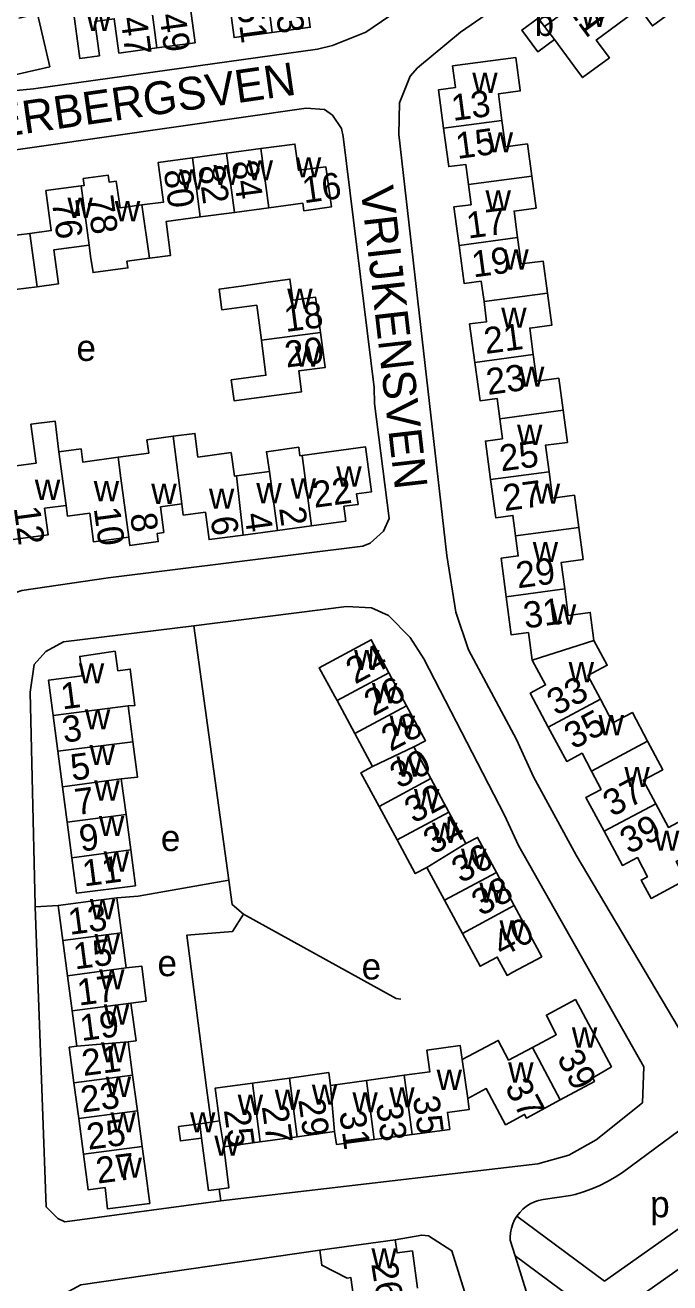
# Model space of a CAD drawing. Extents: x 162667 to 164645, y 379003 to 382150.
# Drawn here: x 163598 to 163696.1, y 381098.1 to 381289.7 of the extents above; entities that cross this region are included whole.
import ezdxf

# ---------------------------------------------------------------- set-up
doc = ezdxf.new("R2010")
doc.units = 0
for name, color, linetype in [('BLT_Basislijn', 7, 'Continuous'), ('BLT_Bebouwing', 7, 'Continuous'), ('BLT_Centroide', 7, 'Continuous'), ('BLT_Huisnummer', 7, 'Continuous'), ('BLT_Huisnummer_ tussenligend', 7, 'Continuous'), ('BLT_Onderverdeling_panden', 7, 'Continuous'), ('BLT_Straatnaam', 7, 'Continuous')]:
    doc.layers.add(name, color=color, linetype=linetype)

msp = doc.modelspace()

# ---------------------------------------------------------------- linework, layer by layer
at = {"layer": 'BLT_Basislijn'}
for p, q in [((163664.25, 381288.62), (163682.77, 381301.43)), ((163657.72, 381283.2), (163664.25, 381288.62)), ((163656.59, 381281.91), (163657.72, 381283.2)), ((163654.95, 381277.85), (163656.59, 381281.91)), ((163654.87, 381273.04), (163654.95, 381277.85)), ((163662.19, 381208.9), (163654.87, 381273.04)), ((163663.55, 381200.26), (163662.19, 381208.9)), ((163665.46, 381194.53), (163663.55, 381200.26)), ((163623.65, 381198.19), (163629, 381159.43)), ((163672.79, 381180.88), (163665.46, 381194.53)), ((163675.4, 381175.21), (163672.79, 381180.88)), ((163681.89, 381163.26), (163675.4, 381175.21)), ((163698.35, 381135.41), (163681.89, 381163.26)), ((163603, 381155.59), (163599.49, 381155.39)), ((163698.9, 381122.3), (163688.93, 381114.94)), ((163686.19, 381098.35), (163706.26, 381112.53)), ((163676.84, 381110.81), (163681.01, 381111.4)), ((163672.83, 381108.25), (163686.19, 381098.35)), ((163688.46, 381093.84), (163709.27, 381108.53)), ((163671.82, 381104.61), (163672.58, 381102.22)), ((163672.58, 381102.22), (163701.62, 381010.06))]:
    msp.add_line(p, q, dxfattribs=at)
for points in [[(163704.62, 381348.91), (163712.56, 381338.33), (163712.43, 381333.8), (163710.39, 381331.86), (163675.03, 381306.44), (163666.11, 381299.73), (163649.85, 381288.62), (163644.75, 381286.58), (163642.47, 381286.05), (163599.25, 381280), (163589.15, 381279.05), (163586.28, 381280.4), (163584.72, 381282.62), (163582.01, 381293.43), (163574.46, 381327.24), (163571.73, 381328.85), (163571.41, 381330.34)], [(163583.1, 381270.55), (163587.28, 381269.85), (163590.17, 381269.81), (163640.77, 381277.05), (163643.57, 381276.83), (163644.77, 381275.96), (163646.12, 381273.96), (163646.38, 381272.71), (163651.1, 381234.51), (163651.18, 381232.05), (163653.39, 381214.56), (163652.55, 381212.63), (163650.49, 381210.78), (163649.37, 381210.33), (163610.61, 381205.49), (163597.45, 381203.58), (163592.38, 381201.9)], [(163623.65, 381198.19), (163646.89, 381201.14), (163650.71, 381200.95), (163653.29, 381199.78), (163656.57, 381196.41), (163658.68, 381193.16), (163670.98, 381169.35), (163673.09, 381164.73), (163692.18, 381131.03), (163691.97, 381125.54), (163684.9, 381119.9), (163680.76, 381117.58), (163676.04, 381116.22), (163627.76, 381110.58)], [(163623.65, 381198.19), (163603.81, 381195.76), (163601.09, 381194.3), (163599.33, 381192.3), (163598.72, 381188.1), (163599.48, 381155.59), (163599.49, 381155.39)], [(163629, 381159.43), (163615.18, 381157.02), (163611.92, 381156.78)], [(163631.23, 381154.27), (163629.51, 381155.72), (163629, 381159.43)], [(163599.49, 381155.39), (163601.16, 381109.67), (163602.92, 381107.89), (163604.01, 381107.39), (163627.76, 381110.58)], [(163626.27, 381122.59), (163625.59, 381127.82), (163622.61, 381151.08), (163629.55, 381151.64), (163631.23, 381154.27)], [(163631.23, 381154.27), (163654.48, 381141.43), (163655.17, 381141.31)], [(163688.93, 381114.94), (163687.82, 381114.2), (163686.67, 381113.53), (163685.48, 381112.93), (163684.26, 381112.41), (163683.01, 381111.95), (163681.73, 381111.58), (163681.01, 381111.4)], [(163627.76, 381110.58), (163627.53, 381112.4)], [(163676.84, 381110.81), (163676.16, 381110.66), (163675.51, 381110.44), (163674.89, 381110.14), (163674.31, 381109.77), (163673.77, 381109.34), (163673.29, 381108.85), (163672.83, 381108.25)], [(163672.83, 381108.25), (163672.5, 381107.71), (163672.22, 381107.08), (163672.01, 381106.43), (163671.87, 381105.75), (163671.82, 381105.06), (163671.82, 381104.61)], [(163654.3, 381104.67), (163658.36, 381105.39), (163659.41, 381105.28), (163662.92, 381103.01), (163692.54, 381007.91)], [(163615.57, 381000.96), (163602.69, 381093.3), (163604.03, 381096.48), (163606.45, 381097.82), (163642.82, 381103.11)], [(163672.58, 381102.22), (163683.03, 381094.47), (163694.24, 381058.06)]]:
    msp.add_lwpolyline(points, dxfattribs=at)
at = {"layer": 'BLT_Bebouwing'}
for p, q in [((163628.65, 381270.18), (163623.44, 381269.49)), ((163633.85, 381270.88), (163628.65, 381270.18)), ((163635.05, 381261.86), (163629.85, 381261.17)), ((163629.85, 381261.17), (163624.64, 381260.48)), ((163612.51, 381220.7), (163612.13, 381223.87)), ((163630.15, 381221.04), (163635.17, 381221.72)), ((163600.91, 381216.09), (163604.2, 381216.54)), ((163618.55, 381216.31), (163621.83, 381216.75)), ((163636.39, 381212.73), (163631.18, 381212.02)), ((163641.59, 381213.43), (163636.39, 381212.73)), ((163653.36, 381191.05), (163656.06, 381186.03)), ((163613.64, 381186.01), (163614.37, 381180.54)), ((163645.46, 381186.8), (163648.17, 381181.78)), ((163602.95, 381179.1), (163602.24, 381184.51)), ((163648.17, 381181.78), (163650.87, 381176.76)), ((163657.17, 381179.74), (163659.75, 381174.93)), ((163603.66, 381173.69), (163602.95, 381179.1)), ((163604.37, 381168.28), (163603.66, 381173.69)), ((163612.61, 381174.86), (163613.33, 381169.46)), ((163659.75, 381174.93), (163662.5, 381169.81)), ((163651.85, 381170.69), (163654.61, 381165.57)), ((163662.5, 381169.81), (163665.08, 381165.01)), ((163605.08, 381162.87), (163604.37, 381168.28)), ((163613.33, 381169.46), (163614.04, 381164.05)), ((163659.13, 381161.4), (163661.83, 381156.38)), ((163669.72, 381160.62), (163672.43, 381155.6)), ((163611.92, 381156.78), (163612.64, 381151.42)), ((163661.83, 381156.38), (163664.54, 381151.35)), ((163603.71, 381150.24), (163603, 381155.59)), ((163612.64, 381151.42), (163613.36, 381146.07)), ((163604.42, 381144.88), (163603.71, 381150.24)), ((163605.12, 381139.53), (163604.42, 381144.88)), ((163605.83, 381134.18), (163605.12, 381139.53)), ((163613.65, 381134.82), (163614.33, 381129.77)), ((163614.33, 381129.77), (163615.06, 381124.33)), ((163655.68, 381129.73), (163649.93, 381128.94)), ((163606.13, 381123.14), (163605.4, 381128.57)), ((163638.2, 381129.31), (163632.56, 381128.54)), ((163649.93, 381128.94), (163644.46, 381128.19)), ((163615.06, 381124.33), (163615.79, 381118.9)), ((163606.86, 381117.71), (163606.13, 381123.14)), ((163639.41, 381120.37), (163633.77, 381119.61)), ((163645.05, 381121.14), (163639.41, 381120.37)), ((163656.88, 381120.71), (163651.13, 381119.95)), ((163657.71, 381097.3), (163656.93, 381102.98))]:
    msp.add_line(p, q, dxfattribs=at)
for points in [[(163677.04, 381289.47), (163679.72, 381291.46), (163678.15, 381293.57), (163682.88, 381297.07)], [(163635.59, 381288.58), (163641.37, 381289.36), (163640.75, 381294.12), (163644.78, 381294.65)], [(163608.21, 381292.94), (163605.24, 381292.55), (163606.28, 381284.63), (163609.27, 381285.02), (163608.57, 381290.27)], [(163618.04, 381286.22), (163623.83, 381287), (163623.13, 381292.25), (163626.11, 381292.65)], [(163626.11, 381292.65), (163629.07, 381293.05), (163629.78, 381287.8), (163635.59, 381288.58)], [(163697.44, 381292.49), (163693.49, 381289.57), (163691.5, 381292.26), (163688.22, 381289.84)], [(163588.21, 381288.69), (163588.9, 381285.76), (163587.44, 381285.42), (163588.07, 381282.65), (163595.16, 381284.3), (163595.71, 381281.95), (163601.7, 381283.35), (163599.83, 381291.4), (163596.99, 381290.74)], [(163608.57, 381290.27), (163611.53, 381290.66), (163612.24, 381285.44), (163618.04, 381286.22)], [(163677.04, 381289.47), (163676.07, 381290.78), (163673.6, 381288.93), (163676.03, 381285.64), (163678.55, 381287.5)], [(163688.22, 381289.84), (163684.94, 381287.42), (163686.93, 381284.73), (163682.84, 381281.7), (163681.52, 381283.48), (163678.55, 381287.5)], [(163661.67, 381273.99), (163660.89, 381279.82), (163663.49, 381280.18), (163663.06, 381283.47), (163672.68, 381284.75), (163673.35, 381279.79), (163673.37, 381279.67), (163670.03, 381279.22), (163670.57, 381275.19)], [(163675.1, 381266.71), (163674.45, 381271.6), (163671.11, 381271.15), (163670.57, 381275.19)], [(163665.46, 381265.42), (163665.06, 381268.49), (163662.46, 381268.16), (163661.67, 381273.99)], [(163635.05, 381261.86), (163640.26, 381262.55), (163640.41, 381261.42), (163644.59, 381262), (163643.73, 381268.12), (163639.58, 381267.58), (163639.05, 381271.58), (163633.85, 381270.88)], [(163623.44, 381269.49), (163618.23, 381268.79), (163618.89, 381263.83), (163619.04, 381262.74), (163615.72, 381262.3)], [(163612.45, 381261.86), (163611.83, 381265.92), (163610.76, 381265.77), (163610.62, 381266.83), (163606.8, 381266.32), (163606.94, 381265.26), (163606.48, 381265.2)], [(163664.05, 381256.15), (163663.26, 381262), (163665.86, 381262.34), (163665.46, 381265.42)], [(163672.96, 381257.34), (163672.42, 381261.38), (163675.76, 381261.82), (163675.1, 381266.71)], [(163606.48, 381265.2), (163601.13, 381264.48), (163601.94, 381258.41), (163598.68, 381257.97)], [(163589.45, 381260.88), (163594.8, 381261.59), (163595.34, 381257.53), (163598.68, 381257.97)], [(163615.72, 381262.3), (163612.45, 381261.86)], [(163616.88, 381254.18), (163620.12, 381254.61), (163619.43, 381259.78), (163624.64, 381260.48)], [(163599.78, 381249.85), (163603.04, 381250.28), (163602.34, 381255.47), (163607.69, 381256.19)], [(163607.69, 381256.19), (163607.92, 381254.48), (163608.31, 381251.99), (163613.61, 381252.7), (163613.47, 381253.72), (163616.88, 381254.18)], [(163667.84, 381247.58), (163667.52, 381250), (163667.43, 381250.67), (163664.84, 381250.33), (163664.05, 381256.15)], [(163677.49, 381248.87), (163676.84, 381253.76), (163673.5, 381253.31), (163672.96, 381257.34)], [(163599.78, 381249.85), (163596.42, 381249.4), (163595.99, 381252.6), (163590.65, 381251.89)], [(163633.93, 381241.69), (163633.22, 381247.03), (163627.92, 381246.32), (163627.5, 381249.47), (163631.23, 381250), (163634.96, 381250.53), (163638.29, 381251.01), (163638.72, 381247.78), (163642.2, 381248.24), (163642.92, 381242.88)], [(163675.35, 381239.5), (163674.81, 381243.54), (163678.15, 381243.98), (163677.49, 381248.87)], [(163666.44, 381238.31), (163665.65, 381244.17), (163668.24, 381244.52), (163667.84, 381247.58)], [(163642.92, 381242.88), (163643.63, 381237.54), (163639.63, 381237.01), (163640.05, 381233.84), (163629.78, 381232.48), (163629.36, 381235.65), (163634.64, 381236.35), (163633.93, 381241.69)], [(163679.88, 381231.02), (163679.23, 381235.91), (163675.89, 381235.47), (163675.35, 381239.5)], [(163670.24, 381229.74), (163669.83, 381232.84), (163667.23, 381232.49), (163666.44, 381238.31)], [(163677.74, 381221.66), (163677.2, 381225.69), (163680.54, 381226.14), (163679.88, 381231.02)], [(163594.66, 381222.33), (163599.64, 381222.95), (163598.85, 381228.9), (163602.52, 381229.38), (163603.1, 381224.68)], [(163668.84, 381220.47), (163668.05, 381226.34), (163670.65, 381226.69), (163670.24, 381229.74)], [(163612.13, 381223.87), (163616.79, 381224.5), (163616.51, 381226.52), (163620.5, 381227.06)], [(163620.5, 381227.06), (163623.81, 381227.5), (163624.28, 381223.9), (163629.33, 381224.59)], [(163603.1, 381224.68), (163606.47, 381225.15), (163606.74, 381223.13), (163612.13, 381223.87)], [(163635.17, 381221.72), (163634.71, 381224.72), (163639.63, 381225.39), (163639.8, 381224.09), (163640.14, 381224.14)], [(163646.47, 381216.42), (163648.67, 381216.69), (163648.44, 381218.3), (163650.69, 381218.6), (163649.77, 381225.47), (163640.14, 381224.14)], [(163629.33, 381224.59), (163629.82, 381221), (163630.15, 381221.04)], [(163682.27, 381213.19), (163681.62, 381218.08), (163678.28, 381217.63), (163677.74, 381221.66)], [(163672.65, 381211.9), (163672.23, 381215), (163669.63, 381214.65), (163668.84, 381220.47)], [(163596.12, 381211.32), (163601.46, 381212.05), (163600.91, 381216.09)], [(163604.2, 381216.54), (163604.41, 381214.92), (163607.79, 381215.37)], [(163613.73, 381211.69), (163613.9, 381210.44), (163618.24, 381211.03), (163618.07, 381212.28), (163619.07, 381212.41), (163618.55, 381216.31)], [(163621.83, 381216.75), (163622.04, 381215.07), (163625.42, 381215.52)], [(163646.47, 381216.42), (163646.78, 381214.14), (163641.59, 381213.43)], [(163607.79, 381215.37), (163608.38, 381210.97), (163613.73, 381211.69)], [(163631.18, 381212.02), (163625.98, 381211.32), (163625.42, 381215.52)], [(163671.23, 381202.63), (163670.45, 381208.48), (163673.06, 381208.83), (163672.65, 381211.9)], [(163680.14, 381203.83), (163679.6, 381207.86), (163682.92, 381208.3), (163682.27, 381213.19)], [(163675.19, 381192.95), (163674.61, 381197.17), (163672, 381196.81), (163671.23, 381202.63)], [(163684.57, 381195.97), (163684.01, 381200.24), (163680.68, 381199.79), (163680.14, 381203.83)], [(163653.36, 381191.05), (163650.66, 381196.07), (163642.76, 381191.81), (163645.13, 381187.41), (163645.46, 381186.8)], [(163685.57, 381187), (163683.65, 381190.61), (163686.61, 381192.18), (163684.57, 381195.97)], [(163602.24, 381184.51), (163601.53, 381189.92), (163606.65, 381190.6), (163606.27, 381193.54), (163611.67, 381194.33), (163612.1, 381191.36), (163613.96, 381191.61), (163614.68, 381186.08), (163613.64, 381186.01)], [(163677.63, 381182.78), (163674.87, 381187.93), (163677.21, 381189.19), (163675.19, 381192.95)], [(163692.76, 381180.61), (163690.44, 381184.97), (163687.48, 381183.39), (163685.57, 381187)], [(163656.06, 381186.03), (163658.94, 381180.69), (163657.17, 381179.74)], [(163684.21, 381176.07), (163682.77, 381178.78), (163680.44, 381177.55), (163677.63, 381182.78)], [(163614.37, 381180.54), (163615.08, 381175.16), (163612.61, 381174.86)], [(163694.01, 381171.08), (163692.09, 381174.68), (163695.07, 381176.26), (163692.76, 381180.61)], [(163650.87, 381176.76), (163649.1, 381175.81), (163651.85, 381170.69)], [(163686.12, 381166.89), (163683.36, 381172.05), (163685.68, 381173.28), (163684.21, 381176.07)], [(163694.01, 381171.08), (163695.92, 381167.49), (163698.9, 381169.07), (163701.3, 381164.56), (163697.08, 381162.31), (163698.58, 381159.5), (163697.69, 381159.03), (163693.28, 381156.68), (163691.77, 381159.46), (163692.73, 381159.96), (163691.21, 381162.88), (163688.91, 381161.69), (163686.12, 381166.89)], [(163665.08, 381165.01), (163666.85, 381165.96), (163669.72, 381160.62)], [(163614.04, 381164.05), (163614.76, 381158.61), (163605.79, 381157.46), (163605.08, 381162.87)], [(163654.61, 381165.57), (163657.36, 381160.44), (163659.13, 381161.4)], [(163603, 381155.59), (163607.96, 381156.25), (163611.92, 381156.78)], [(163664.54, 381151.35), (163667.24, 381146.33), (163669.85, 381147.74), (163671.35, 381144.95), (163672.24, 381145.42), (163676.64, 381147.79), (163672.43, 381155.6)], [(163613.36, 381146.07), (163615.71, 381146.36), (163616.38, 381141.01), (163614.08, 381140.72)], [(163679.43, 381125.98), (163684.66, 381128.8), (163684.4, 381129.34), (163687.23, 381131.02), (163681.77, 381141.25), (163677.35, 381138.91), (163678.83, 381135.89), (163675.21, 381133.97)], [(163614.08, 381140.72), (163614.85, 381134.98), (163613.65, 381134.82)], [(163605.4, 381128.57), (163604.68, 381134.01), (163605.83, 381134.18)], [(163664.52, 381132.13), (163664.22, 381134.26), (163659.15, 381133.56), (163659.6, 381130.27), (163655.68, 381129.73)], [(163675.21, 381133.97), (163671.58, 381132.05), (163670.01, 381135.03), (163664.52, 381132.13)], [(163644.46, 381128.19), (163644.19, 381130.14), (163638.2, 381129.31)], [(163632.56, 381128.54), (163626.89, 381127.76), (163627.58, 381122.77)], [(163679.43, 381125.98), (163674.31, 381123.22), (163674.01, 381123.76), (163671.12, 381122.19), (163668.19, 381127.7), (163665.36, 381126.19)], [(163665.36, 381126.19), (163665.57, 381124.5), (163662.28, 381124.08), (163662.63, 381121.48), (163656.88, 381120.71)], [(163624.54, 381122.35), (163621.32, 381121.91), (163621.62, 381119.72), (163624.83, 381120.16)], [(163626.27, 381122.59), (163624.54, 381122.35)], [(163627.58, 381122.77), (163626.27, 381122.59)], [(163624.83, 381120.16), (163625.89, 381112.18), (163627.53, 381112.4)], [(163651.13, 381119.95), (163645.38, 381119.18), (163645.05, 381121.14)], [(163615.79, 381118.9), (163616.28, 381115.18), (163616.94, 381110.22), (163610.52, 381109.37), (163610.13, 381112.61), (163607.58, 381112.27), (163606.86, 381117.71)], [(163627.53, 381112.4), (163629, 381112.59), (163628.2, 381118.85)], [(163628.2, 381118.85), (163633.77, 381119.61)], [(163654.3, 381104.67), (163642.82, 381103.11)], [(163656.93, 381102.98), (163654.59, 381102.66), (163654.3, 381104.67)], [(163642.82, 381103.11), (163643.14, 381100.79), (163646.98, 381098.84), (163647.58, 381098.92), (163647.99, 381095.96)]]:
    msp.add_lwpolyline(points, dxfattribs=at)
at = {"layer": 'BLT_Onderverdeling_panden'}
for p, q in [((163618.04, 381286.22), (163616.64, 381296.6)), ((163634.38, 381297.48), (163635.59, 381288.58)), ((163670.57, 381275.19), (163661.67, 381273.99)), ((163624.64, 381260.48), (163623.44, 381269.49)), ((163629.85, 381261.17), (163628.65, 381270.18)), ((163635.05, 381261.86), (163633.85, 381270.88)), ((163675.1, 381266.71), (163665.46, 381265.42)), ((163606.48, 381265.2), (163607.69, 381256.19)), ((163615.72, 381262.3), (163616.88, 381254.18)), ((163598.68, 381257.97), (163599.78, 381249.85)), ((163672.96, 381257.34), (163664.05, 381256.15)), ((163677.49, 381248.87), (163667.84, 381247.58)), ((163633.93, 381241.69), (163642.92, 381242.88)), ((163675.35, 381239.5), (163666.44, 381238.31)), ((163679.88, 381231.02), (163670.24, 381229.74)), ((163621.83, 381216.75), (163620.5, 381227.06)), ((163603.1, 381224.68), (163604.2, 381216.54)), ((163641.59, 381213.43), (163640.14, 381224.14)), ((163636.39, 381212.73), (163635.17, 381221.72)), ((163677.74, 381221.66), (163668.84, 381220.47)), ((163612.51, 381220.7), (163613.73, 381211.69)), ((163631.18, 381212.02), (163630.15, 381221.04)), ((163682.27, 381213.19), (163672.65, 381211.9)), ((163680.14, 381203.83), (163671.23, 381202.63)), ((163675.19, 381192.95), (163684.57, 381195.97)), ((163653.36, 381191.05), (163645.46, 381186.8)), ((163685.57, 381187), (163677.63, 381182.78)), ((163613.64, 381186.01), (163602.24, 381184.51)), ((163656.06, 381186.03), (163648.17, 381181.78)), ((163614.37, 381180.54), (163602.95, 381179.1)), ((163650.87, 381176.76), (163657.17, 381179.74)), ((163692.76, 381180.61), (163684.21, 381176.07)), ((163612.61, 381174.86), (163603.66, 381173.69)), ((163659.75, 381174.93), (163651.85, 381170.69)), ((163662.5, 381169.81), (163654.61, 381165.57)), ((163694.01, 381171.08), (163686.12, 381166.89)), ((163613.33, 381169.46), (163604.37, 381168.28)), ((163614.04, 381164.05), (163605.08, 381162.87)), ((163665.08, 381165.01), (163659.13, 381161.4)), ((163669.72, 381160.62), (163661.83, 381156.38)), ((163672.43, 381155.6), (163664.54, 381151.35)), ((163612.64, 381151.42), (163603.71, 381150.24)), ((163613.36, 381146.07), (163604.42, 381144.88)), ((163614.08, 381140.72), (163605.12, 381139.53)), ((163605.83, 381134.18), (163613.65, 381134.82)), ((163675.21, 381133.97), (163679.43, 381125.98)), ((163664.52, 381132.13), (163665.36, 381126.19)), ((163614.33, 381129.77), (163605.4, 381128.57)), ((163656.88, 381120.71), (163655.68, 381129.73)), ((163633.77, 381119.61), (163632.56, 381128.54)), ((163639.41, 381120.37), (163638.2, 381129.31)), ((163644.46, 381128.19), (163645.05, 381121.14)), ((163651.13, 381119.95), (163649.93, 381128.94)), ((163615.06, 381124.33), (163606.13, 381123.14)), ((163624.54, 381122.35), (163624.83, 381120.16)), ((163627.58, 381122.77), (163628.2, 381118.85)), ((163615.79, 381118.9), (163606.86, 381117.71))]:
    msp.add_line(p, q, dxfattribs=at)
msp.add_lwpolyline([(163678.55, 381287.5), (163677.04, 381289.47)], dxfattribs=at)

# ---------------------------------------------------------------- texts
at = {"layer": 'BLT_Centroide'}
for s, p in [('b', (163675.54, 381288.05)), ('w', (163682.62, 381289.42)), ('w', (163607.25, 381288.78)), ('w', (163666.05, 381279.38)), ('w', (163668.4, 381270.31)), ('w', (163639.2, 381266.5)), ('w', (163621.44, 381264.64)), ('w', (163626.64, 381265.33)), ('w', (163631.84, 381266.03)), ('w', (163668.07, 381261.44)), ('w', (163604.41, 381260.33)), ('w', (163611.62, 381259.81)), ('w', (163670.78, 381252.47)), ('w', (163637.87, 381246.47)), ('w', (163670.46, 381243.59)), ('e', (163605.77, 381238.54)), ('w', (163639.03, 381237.69)), ('w', (163673.17, 381234.62)), ('w', (163672.87, 381225.75)), ('w', (163645.34, 381219.41)), ('w', (163599.44, 381217.36)), ('w', (163608.41, 381217.17)), ('w', (163617.17, 381216.75)), ('w', (163633.17, 381216.86)), ('w', (163638.38, 381217.58)), ('w', (163675.57, 381216.78)), ('w', (163625.95, 381216.03)), ('w', (163675.26, 381207.91)), ('w', (163678.02, 381198.38)), ('w', (163648.06, 381191.44)), ('w', (163680.73, 381189.59)), ('w', (163606.14, 381189.41)), ('w', (163650.77, 381186.41)), ('w', (163607.07, 381182.41)), ('w', (163653.47, 381181.41)), ('w', (163685.28, 381181.53)), ('w', (163607.77, 381176.97)), ('w', (163654.51, 381175.22)), ('w', (163689.22, 381173.62)), ('w', (163608.49, 381171.56)), ('w', (163657.18, 381170.25)), ('w', (163609.2, 381166.16)), ('w', (163659.93, 381165.12)), ('e', (163618.63, 381163.88)), ('w', (163693.72, 381163.92)), ('w', (163609.92, 381160.75)), ('w', (163664.34, 381161.16)), ('w', (163667.13, 381156)), ('w', (163607.82, 381153.5)), ('w', (163670.2, 381150.28)), ('w', (163608.53, 381148.16)), ('e', (163618.12, 381144.82)), ('e', (163649.2, 381144.32)), ('w', (163609.24, 381142.81)), ('w', (163609.95, 381137.44)), ('w', (163681.22, 381133.95)), ('w', (163609.52, 381131.69)), ('w', (163671.52, 381128.62)), ('w', (163610.23, 381126.44)), ('w', (163660.62, 381127.5)), ('w', (163635.98, 381124.45)), ('w', (163641.62, 381125.23)), ('w', (163653.41, 381124.83)), ('w', (163630.33, 381123.69)), ('w', (163647.8, 381124.08)), ('w', (163610.96, 381121.03)), ('w', (163623.07, 381121.03)), ('w', (163626.77, 381117.47)), ('w', (163611.88, 381114.12)), ('p', (163693.14, 381108.1)), ('w', (163650.69, 381100.31))]:
    msp.add_text(s, height=4, dxfattribs=at).set_placement(p)
at = {"layer": 'BLT_Huisnummer'}
for s, rotation, p in [('53', 277.659, (163635.8, 381294.1)), ('11', 306.4758, (163680.25, 381292.44)), ('47', 277.7456, (163612.48, 381290.76)), ('13', 7.6441, (163663.13, 381275.09)), ('80', 277.5742, (163619.06, 381267.53)), ('84', 277.5759, (163629.43, 381268.88)), ('16', 7.9629, (163640.43, 381262.55)), ('78', 277.6705, (163607.38, 381263.53)), ('76', 277.6705, (163602.02, 381262.8)), ('17', 7.6441, (163665.43, 381257.17)), ('18', 7.5458, (163637.65, 381242.94)), ('21', 7.6441, (163668.09, 381239.59)), ('20', 7.5401, (163637.74, 381237.52)), ('25', 7.6441, (163670.46, 381221.71)), ('22', 7.713, (163642, 381216.16)), ('10', 277.6764, (163608.4, 381216.07)), ('2', 277.7006, (163636.62, 381216.13)), ('6', 277.7006, (163626.19, 381214.68)), ('29', 7.6441, (163672.98, 381203.89)), ('24', 28.2822, (163648.21, 381189.23)), ('1', 7.4705, (163603.64, 381185.44)), ('33', 28.0101, (163678.81, 381184.42)), ('28', 28.3123, (163653.6, 381178.96)), ('5', 7.4705, (163605.12, 381174.6)), ('32', 28.3123, (163657.13, 381168.01)), ('9', 7.4705, (163606.45, 381163.79)), ('39', 28.0089, (163689.92, 381163.33)), ('36', 28.3123, (163664.32, 381158.9)), ('13', 7.4705, (163604.76, 381151.11)), ('40', 28.3123, (163670.59, 381147.65)), ('17', 7.4705, (163606.15, 381140.33)), ('21', 7.4705, (163606.84, 381129.61)), ('39', 297.8501, (163678.86, 381132.38)), ('37', 298.039, (163670.92, 381127.92)), ('29', 277.8446, (163639.55, 381126.01)), ('35', 277.8446, (163657, 381126.4)), ('25', 277.8446, (163628.21, 381124.44)), ('27', 7.4705, (163609, 381113.21)), ('26', 279.0976, (163650.65, 381101.01))]:
    msp.add_text(s, height=4, rotation=rotation, dxfattribs=at).set_placement(p)
at = {"layer": 'BLT_Huisnummer_ tussenligend'}
for s, rotation, p in [('51', 277.7456, (163630.16, 381292.67)), ('49', 277.7456, (163618.39, 381291.27)), ('15', 7.6441, (163663.79, 381269.3)), ('82', 277.5742, (163624.32, 381268.17)), ('19', 7.6441, (163666.22, 381251.25)), ('23', 7.6441, (163668.43, 381233.35)), ('27', 7.6441, (163670.97, 381215.66)), ('12', 277.6746, (163596.22, 381216.2)), ('8', 277.6764, (163613.93, 381215.18)), ('4', 277.7006, (163631.36, 381215.22)), ('31', 7.6441, (163674.09, 381197.77)), ('26', 28.2822, (163650.98, 381184.36)), ('35', 28.0101, (163681.43, 381179.29)), ('3', 7.4705, (163603.86, 381180.38)), ('30', 28.3123, (163654.91, 381173.3)), ('7', 7.4705, (163605.76, 381169.34)), ('37', 28.0101, (163687.34, 381169.02)), ('34', 28.3123, (163660.01, 381163.27)), ('11', 7.4705, (163606.93, 381158.48)), ('38', 28.3123, (163667.36, 381153.9)), ('15', 7.4705, (163605.55, 381145.84)), ('19', 7.4705, (163606.56, 381134.93)), ('23', 7.4705, (163606.65, 381124.03)), ('33', 277.8446, (163651.38, 381125.35)), ('27', 277.8446, (163633.99, 381124.98)), ('31', 277.8446, (163645.79, 381124.11)), ('25', 7.4705, (163607.58, 381118.37))]:
    msp.add_text(s, height=4, rotation=rotation, dxfattribs=at).set_placement(p)
at = {"layer": 'BLT_Straatnaam'}
for s, rotation, p in [('MEERBERGSVEN', 8.2142, (163583.53, 381271.06)), ('VRIJKENSVEN', 276.5357, (163649.03, 381264.91))]:
    msp.add_text(s, height=5, rotation=rotation, dxfattribs=at).set_placement(p)

doc.saveas('drawing.dxf')
